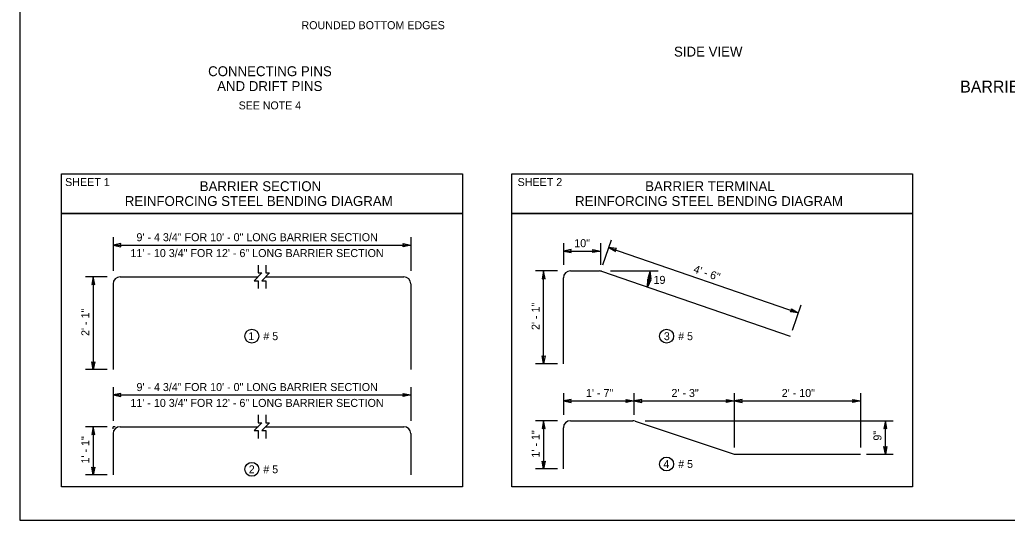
# Model space of a CAD drawing. Extents: x 99862 to 103680, y 99470 to 105076.
# Drawn here: x 99862 to 101836, y 103000 to 104000 of the extents above; entities that cross this region are included whole.
import ezdxf

# ---------------------------------------------------------------- set-up
doc = ezdxf.new("R2010")
doc.units = 0
for name, color, linetype in [('Level 1', 7, 'Continuous'), ('Level 10', 7, 'Continuous'), ('Level 15', 7, 'Continuous'), ('Level 20', 7, 'Continuous'), ('Level 40', 7, 'Continuous'), ('Level 60', 7, 'Continuous')]:
    doc.layers.add(name, color=color, linetype=linetype)

msp = doc.modelspace()

# ---------------------------------------------------------------- linework, layer by layer
at = {"layer": 'Level 1'}
msp.add_lwpolyline([(99862, 102999.5), (103151, 102999.5), (103151, 105075.5), (99862, 105075.5)], close=True, dxfattribs=at)
at = {"layer": 'Level 10'}
for p, q in [((100062.5, 103486.2), (100338.4, 103486.2)), ((100353.8, 103486.2), (100629.7, 103486.2)), ((100948.6, 103312.4), (100948.6, 103484.1)), ((100962.5, 103498.1), (101020.5, 103498.1)), ((101025, 103497.3), (101401.9, 103367.5)), ((100048.5, 103472.3), (100048.5, 103300.6)), ((100643.6, 103472.3), (100643.6, 103300.6)), ((100062.5, 103186.6), (100338.4, 103186.6)), ((100353.8, 103186.6), (100629.7, 103186.6)), ((100948.6, 103102), (100948.6, 103184.6)), ((100962.5, 103198.5), (101087.4, 103198.5)), ((101091.8, 103197.8), (101288, 103132.4)), ((100048.5, 103172.7), (100048.5, 103090.1)), ((100643.6, 103172.7), (100643.6, 103090.1)), ((101292.4, 103131.7), (101542.6, 103131.7))]:
    msp.add_line(p, q, dxfattribs=at)
for centre, start, end in [((100062.5, 103472.3), 90, 180), ((100629.7, 103472.3), 0, 90), ((100962.5, 103484.1), 90, 180), ((101020.5, 103484.1), 71, 90), ((100062.5, 103172.7), 90, 180), ((100629.7, 103172.7), 0, 90), ((100962.5, 103184.6), 90, 180), ((101087.4, 103184.6), 71.5651, 90), ((101292.4, 103145.6), 251.5651, 270)]:
    msp.add_arc(centre, 13.9, start, end, dxfattribs=at)
at = {"layer": 'Level 15'}
for p, q in [((100048.5, 103565.4), (100048.5, 103498.1)), ((100643.6, 103565.4), (100643.6, 103498.1)), ((101044.1, 103559.8), (101026.7, 103509.3)), ((100048.5, 103549.5), (100643.6, 103549.5)), ((100948.6, 103553.5), (100948.6, 103509.9)), ((101022.8, 103553.5), (101022.8, 103509.9)), ((101038.9, 103544.9), (101418, 103414.3)), ((100948.6, 103537.7), (101022.8, 103537.7)), ((100036.7, 103486.2), (99993.1, 103486.2)), ((100008.9, 103486.2), (100008.9, 103300.6)), ((100936.7, 103498.1), (100893.1, 103498.1)), ((100909, 103312.4), (100909, 103498.1)), ((101042.4, 103498.1), (101137.7, 103498.1)), ((101423.2, 103429.3), (101405.8, 103378.8)), ((100936.7, 103312.4), (100893.1, 103312.4)), ((100036.7, 103300.6), (99993.1, 103300.6)), ((100048.5, 103265.8), (100048.5, 103198.5)), ((100643.6, 103265.8), (100643.6, 103198.5)), ((100048.5, 103250), (100643.6, 103250)), ((100948.6, 103253.9), (100948.6, 103210.4)), ((101089.6, 103253.9), (101089.6, 103210.4)), ((101290.1, 103253.9), (101290.1, 103145)), ((101542.6, 103253.9), (101542.6, 103145)), ((100948.6, 103238.1), (101089.6, 103238.1)), ((101089.6, 103238.1), (101290.1, 103238.1)), ((101290.1, 103238.1), (101542.6, 103238.1)), ((100036.7, 103186.6), (99993.1, 103186.6)), ((100008.9, 103186.6), (100008.9, 103090.1)), ((100048.5, 103182.6), (100048.5, 103186.6)), ((100052.6, 103186.6), (100048.5, 103186.6)), ((100936.7, 103198.5), (100893.1, 103198.5)), ((100909, 103198.5), (100909, 103102)), ((101111.9, 103198.5), (101607.9, 103198.5)), ((101592.1, 103131.7), (101592.1, 103198.5)), ((101554.4, 103131.7), (101607.9, 103131.7)), ((100036.7, 103090.1), (99993.1, 103090.1)), ((100936.7, 103102), (100893.1, 103102))]:
    msp.add_line(p, q, dxfattribs=at)
for points in [[(100048.5, 103549.5), (100064.1, 103546.5), (100063.4, 103549.5), (100064.1, 103552.6)], [(100643.6, 103549.5), (100628.1, 103546.5), (100628.8, 103549.5), (100628.1, 103552.6)], [(100948.6, 103537.7), (100964.1, 103534.6), (100963.4, 103537.7), (100964.1, 103540.7)], [(101022.8, 103537.7), (101007.2, 103534.6), (101008, 103537.7), (101007.2, 103540.7)], [(101038.9, 103544.9), (101052.7, 103536.9), (101053, 103540), (101054.6, 103542.7)], [(100008.9, 103486.2), (100005.9, 103470.6), (100008.9, 103471.3), (100012, 103470.6)], [(100909, 103498.1), (100905.9, 103482.5), (100909, 103483.2), (100912, 103482.5)], [(101116.4, 103465.8), (101117.4, 103481.7), (101120.2, 103480.2), (101123.3, 103480.1)], [(101121.8, 103498.1), (101117.6, 103482.8), (101120.7, 103483.3), (101123.7, 103482.3)], [(101418, 103414.3), (101402.3, 103416.5), (101404, 103419.2), (101404.3, 103422.3)], [(100909, 103312.4), (100905.9, 103328), (100909, 103327.3), (100912, 103328)], [(100008.9, 103300.6), (100005.9, 103316.1), (100008.9, 103315.4), (100012, 103316.1)], [(100048.5, 103250), (100064.1, 103246.9), (100063.4, 103250), (100064.1, 103253)], [(100643.6, 103250), (100628.1, 103246.9), (100628.8, 103250), (100628.1, 103253)], [(100948.6, 103238.1), (100964.1, 103235), (100963.4, 103238.1), (100964.1, 103241.1)], [(101089.6, 103238.1), (101074.1, 103235), (101074.8, 103238.1), (101074.1, 103241.1)], [(101089.6, 103238.1), (101105.2, 103235), (101104.5, 103238.1), (101105.2, 103241.1)], [(101290.1, 103238.1), (101274.5, 103235), (101275.3, 103238.1), (101274.5, 103241.1)], [(101290.1, 103238.1), (101305.7, 103235), (101305, 103238.1), (101305.7, 103241.1)], [(101542.6, 103238.1), (101527, 103235), (101527.7, 103238.1), (101527, 103241.1)], [(100008.9, 103186.6), (100005.9, 103171), (100008.9, 103171.8), (100012, 103171)], [(100909, 103198.5), (100905.9, 103182.9), (100909, 103183.6), (100912, 103182.9)], [(101592.1, 103198.5), (101589, 103182.9), (101592.1, 103183.6), (101595.1, 103182.9)], [(101592.1, 103131.7), (101589, 103147.2), (101592.1, 103146.5), (101595.1, 103147.2)], [(100008.9, 103090.1), (100005.9, 103105.7), (100008.9, 103104.9), (100012, 103105.7)], [(100909, 103102), (100905.9, 103117.5), (100909, 103116.8), (100912, 103117.5)]]:
    msp.add_lwpolyline(points, close=True, dxfattribs=at)
for points in [[(100338.4, 103509.7), (100338.4, 103493.9), (100346.1, 103493.9), (100330.8, 103478.5), (100338.4, 103478.5), (100338.4, 103462.7)], [(100353.8, 103509.7), (100353.8, 103493.9), (100361.4, 103493.9), (100346.1, 103478.5), (100353.8, 103478.5), (100353.8, 103462.7)], [(100338.4, 103210.1), (100338.4, 103194.3), (100346.1, 103194.3), (100330.8, 103178.9), (100338.4, 103178.9), (100338.4, 103163.1)], [(100353.8, 103210.1), (100353.8, 103194.3), (100361.4, 103194.3), (100346.1, 103178.9), (100353.8, 103178.9), (100353.8, 103163.1)]]:
    msp.add_lwpolyline(points, dxfattribs=at)
msp.add_arc((101022.8, 103498.1), 99, 341, 0, dxfattribs=at)
at = {"layer": 'Level 20'}
for centre in [(100325.7, 103367.5), (101154.8, 103367.5), (101154.8, 103111.9), (100325.7, 103101.4)]:
    msp.add_circle(centre, 13.9, dxfattribs=at)
at = {"layer": 'Level 40'}
for points in [[(99945.6, 103692.1), (100746.6, 103692.1), (100746.6, 103612.9), (99945.6, 103612.9)], [(100845.6, 103692.1), (101646.6, 103692.1), (101646.6, 103612.9), (100845.6, 103612.9)], [(99945.6, 103612.9), (100746.6, 103612.9), (100746.6, 103066), (99945.6, 103066)], [(100845.6, 103612.9), (101646.6, 103612.9), (101646.6, 103066), (100845.6, 103066)]]:
    msp.add_lwpolyline(points, close=True, dxfattribs=at)
at = {"layer": 'Level 60'}
msp.add_line((99862, 102999.5), (99862, 102999.5), dxfattribs=at)

# ---------------------------------------------------------------- texts
at = {"layer": 'Level 20'}
for s, height, p in [('ROUNDED BOTTOM EDGES', 16, (100425, 103981.3)), ('SIDE VIEW', 19.8, (101169.6, 103926.6)), ('CONNECTING PINS', 19.8, (100238.5, 103887.4)), ('AND DRIFT PINS', 19.8, (100256.5, 103857.7)), ('BARRIER TERMINAL', 23.76, (101741.6, 103854.7)), ('SEE NOTE 4', 15.84, (100299.5, 103821)), ('SHEET 1', 16, (99952.7, 103667.7)), ('BARRIER SECTION', 19.8, (100221.7, 103657.5)), ('SHEET 2', 16, (100857, 103667.7)), ('BARRIER TERMINAL', 19.8, (101112, 103657.5)), ('REINFORCING STEEL BENDING DIAGRAM', 19.8, (100071.9, 103627.8)), ('REINFORCING STEEL BENDING DIAGRAM', 19.8, (100971.9, 103627.8)), ('9\' - 4 3/4" FOR 10\' - 0" LONG BARRIER SECTION', 16, (100095.3, 103557.4)), ('10"', 16, (100970.3, 103545.5)), ('11\' - 10 3/4" FOR 12\' - 6" LONG BARRIER SECTION', 16, (100083.2, 103525.7)), ('19', 16, (101128.7, 103472.1)), ('1', 15.8, (100318.9, 103359.6)), (' # 5', 15.84, (100343, 103359.6)), ('3', 15.8, (101149.4, 103359.6)), (' # 5', 15.84, (101172.2, 103359.6)), ('9\' - 4 3/4" FOR 10\' - 0" LONG BARRIER SECTION', 16, (100095.3, 103257.8)), ('1\' - 7"', 16, (100993.7, 103245.9)), ('2\' - 3"', 16, (101164.5, 103245.9)), ('2\' - 10"', 16, (101384.9, 103245.9)), ('11\' - 10 3/4" FOR 12\' - 6" LONG BARRIER SECTION', 16, (100083.2, 103226.1)), ('2', 15.8, (100319.8, 103093.5)), (' # 5', 15.84, (100343, 103093.5)), ('4', 15.8, (101148.4, 103104)), (' # 5', 15.84, (101172.2, 103104))]:
    msp.add_text(s, height=height, dxfattribs=at).set_placement(p)
for s, rotation, p in [('4\' - 6"', 341, (101207, 103495.3)), ('2\' - 1"', 90, (100001.1, 103368)), ('2\' - 1"', 90, (100901.1, 103379.9)), ('1\' - 1"', 90, (100001.1, 103113)), ('1\' - 1"', 90, (100901.1, 103124.9)), ('9"', 90, (101584.2, 103158.7))]:
    msp.add_text(s, height=16, rotation=rotation, dxfattribs=at).set_placement(p)

doc.saveas('drawing.dxf')
